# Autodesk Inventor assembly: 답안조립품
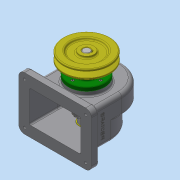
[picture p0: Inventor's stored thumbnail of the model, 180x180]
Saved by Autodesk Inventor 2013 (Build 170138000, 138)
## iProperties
Created: 2017-11
Part Number: 답안조립품
Document SubType Name: Assembly
Designer: dgall
Author: dgall
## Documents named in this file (14)
- C:\Users\dgall\Desktop\471107V1022\답안조립품.iam
- C:\Users\dgall\Desktop\471107V1022\본체.ipt
- C:\Users\dgall\Desktop\471107V1022\축.ipt
- C:\Users\dgall\Desktop\471107V1022\키 - 6 x 6 x 22.ipt
- C:\Users\dgall\Desktop\471107V1022\베어링 6002.ipt
- C:\Users\dgall\Desktop\471107V1022\스퍼기어.ipt
- C:\Users\dgall\Desktop\471107V1022\뒤커버.ipt
- C:\Users\dgall\Desktop\471107V1022\앞커버.ipt
- C:\Users\dgall\Desktop\471107V1022\오일 실 15 30 7.ipt
- C:\Users\dgall\Desktop\471107V1022\키 - 5 x 5 x 18.ipt
- C:\Users\dgall\Desktop\471107V1022\V-벨트풀리.ipt
- C:\Users\dgall\Desktop\471107V1022\멈춤나사 - M4 x 10.ipt
- 멈춤나사 - M4 x 10.ipt
- C:\Users\dgall\Desktop\471107V1022\볼트 M3 x 8.ipt
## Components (1 placed, 1 different names)
1. V-벨트풀리:1
